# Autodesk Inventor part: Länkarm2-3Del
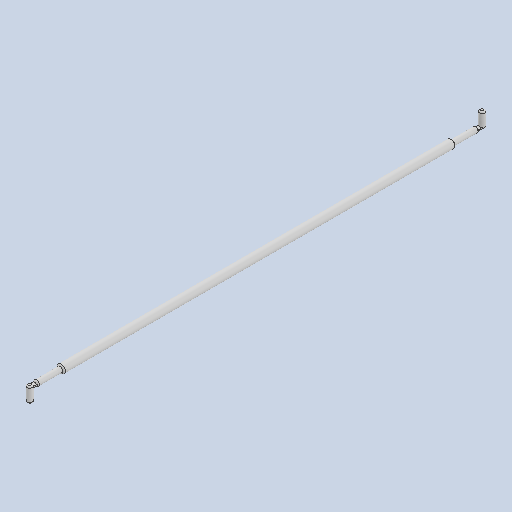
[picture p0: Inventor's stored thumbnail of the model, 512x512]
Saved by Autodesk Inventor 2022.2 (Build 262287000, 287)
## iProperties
Created: 2022-03
Part Number: Länkarm2-3Del
Material: Generic
Document SubType Name: Modeling
Designer: cl
Density: 1 g/cm^3
Appearance: Default
Author: cl
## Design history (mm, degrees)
sketch "Sketch1"
  geometry: L1 (0, 0)-(0, -1609.41); L2 (0, 0)-(-10, 0); L3 (-10, 0)-(-10, -90); L4 (-10, -90)-(-15, -90); L5 (-15, -90)-(-15, -1519.41); L6 (0, -1609.41)-(-10, -1609.41); L7 (-10, -1609.41)-(-10, -1519.41); L8 (-10, -1519.41)-(-15, -1519.41); 1 further point
  constraints: 16 end point, 5 perpendicular, 2 horizontal, 1 midpoint, 1 vertical
  dimensions: "d0" = 1609.41 distance of L1.start L1.end (computed from BladBredd); "d1" = 20 diameter of L3 L1; "d2" = 5 distance between parallel lines of L3 L5; "d3" = 90 distance of L2.end L3.end; "d4" = 20 diameter of L7 L1; "d5" = 90 vertical distance of point (-5, -1609.41) L5.end
revolve "Revolution1" sketch "Sketch1" stored, may be unused: angle "d6" = 90 deg
fillet "Fillet1" dims "d7" = 5
workplane "Work Plane1"
sketch "Sketch2"
  geometry: L1 (10, 0)-(-10, 0) reference; L2 (7.5, 0)-(-7.5, 0); L3 (-7.5, 0)-(-7.5, 20); L4 (-7.5, 20)-(7.5, 20); L5 (7.5, 20)-(7.5, 0); L6 (10, -90)-(10, 0) reference; L7 (10, -1609.41)-(-10, -1609.41) reference; L8 (7.5, -1609.41)-(-7.5, -1609.41); L9 (-7.5, -1609.41)-(-7.5, -1629.41); L10 (-7.5, -1629.41)-(7.5, -1629.41); L11 (7.5, -1629.41)-(7.5, -1609.41); 3 further points
  constraints: 16 end point, 4 parallel, 2 horizontal, 2 perpendicular, 2 point on line, 1 collinear
  dimensions: "d9" = 2.5 distance between parallel lines of L5 L6; "d10" = 15 distance of L3.end L4.end; "d11" = 20 distance of L2.end L3.end; "d12" = 20 distance of L8.end L9.end; "d13" = 15 distance of L9.end L10.end
extrude "Extrusion1" join sketch "Sketch2" distance "d14" = 4; taper "d15" = 0 deg
sketch "Sketch3"
  geometry: L1 (7.5, 20)-(-7.5, 20) reference; L2 (-7.5, -1629.41)-(7.5, -1629.41) reference; C1 r 10 at (0, 20); C2 r 10 at (0, -1629.41); 1 further point
  constraints: 2 centre point, 2 midpoint
  dimensions: "d16" = 20 diameter of C1; "d17" = 20 diameter of C2
extrude "Extrusion2" join sketch "Sketch3" distance "d18" = 8; taper "d20" = 0 deg; dims "d19" = 48, "d21" = 0
extrude "Extrusion3" join sketch "Sketch3" distance "d22" = 50; taper "d24" = 0 deg; dims "d23" = 6, "d25" = 0
fillet "Fillet2" dims "d26" = 5
body "Solid1"
other parameters: "BladBredd" = 987.5, "Fönsterhöjd" = 862, "Blad2" = 1012.5, "Blad3" = 0, "Blad4" = 0, "Blad5" = 1012.5, "Blad6" = 2025, "MGJ12Djup" = 0, "MGJ12Bredd" = 0, "MGJ2Djup" = 0, "MGJ2Bredd" = 5012.5, "MGJ56Djup" = 0, "MGJ56Bredd" = 0, "MGJ23Djup" = 48, "MGJ45Djup" = 48, "GarageRegel5" = 0, "GarageRegel6" = 0, "Styrrulle2Djup" = 0, "FönsterhöjdStyrning" = 862, "FönsterKarm" = 54, "AndraGlasraden" = 0, "BrösthöjdStyrning2" = 0.0001, "InfälldGångDörr" = 0, "Infälldstyr" = 1030.33333, "EnDelGångDörr" = 0, "VinkelJärnStyrSkena" = 1456.25, "d8" = -2
